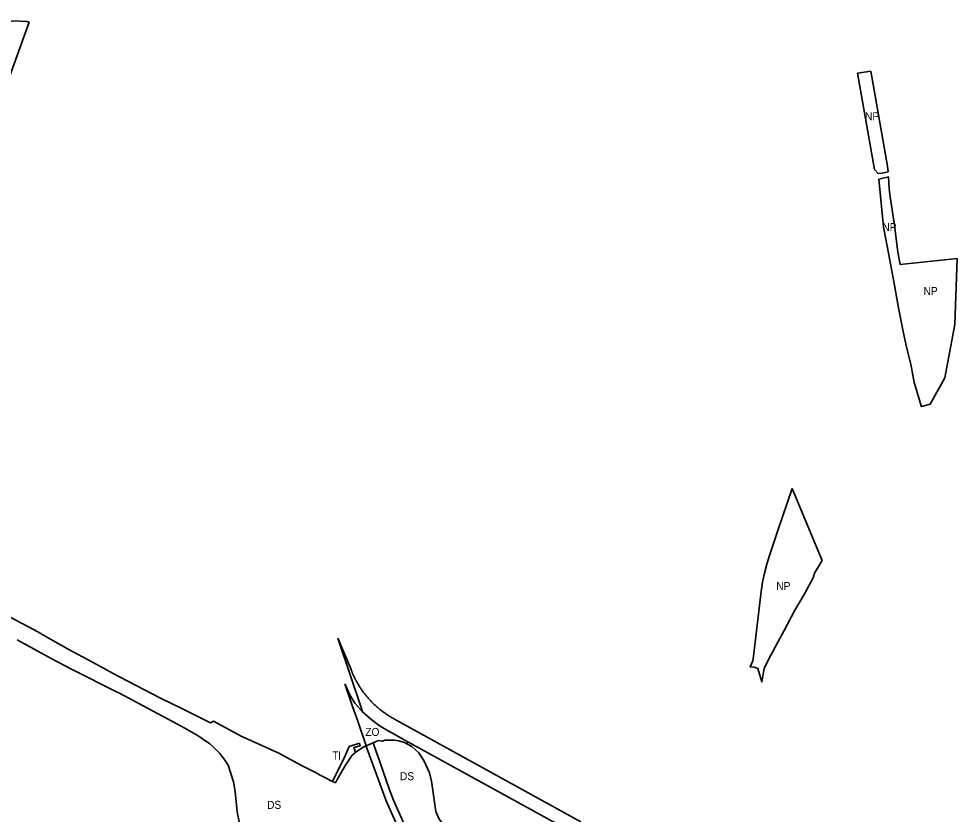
# Model space of a CAD drawing. Extents: x -650971 to -642489, y -1074311 to -1062745.
# Drawn here: x -647077 to -645670, y -1068619 to -1067426 of the extents above; entities that cross this region are included whole.
import ezdxf

# ---------------------------------------------------------------- set-up
doc = ezdxf.new("R2010")
doc.units = 0
doc.header["$LTSCALE"] = 4.8
for name, color, linetype, lineweight in [('24', 7, 'Continuous', 35), ('25', 7, 'Continuous', 35), ('30', 7, 'Continuous', 35), ('42', 7, 'Continuous', 35), ('48', 7, 'Continuous', 35), ('62', 7, 'Continuous', 35)]:
    doc.layers.add(name, color=color, linetype=linetype, lineweight=lineweight)

msp = doc.modelspace()

# ---------------------------------------------------------------- linework, layer by layer
at = {"layer": '24'}
for points in [[(-647099.2, -1068318.27), (-647053.75, -1068342.11), (-647044.93, -1068347.08), (-647040.77, -1068349.4), (-647002.71, -1068371.09), (-646967.64, -1068390), (-646938.95, -1068405.8), (-646936.47, -1068407.23), (-646864.48, -1068444.64), (-646832.29, -1068460.04), (-646789.49, -1068481.31), (-646787.55, -1068480.36), (-646785.05, -1068479.12), (-646743.69, -1068501.76), (-646686.84, -1068526.89), (-646653.21, -1068545.58), (-646631.18, -1068556.77), (-646625.86, -1068559.47), (-646620.94, -1068561.96), (-646606.59, -1068569.33)], [(-646746.32, -1068630.23), (-646749.35, -1068615.18), (-646752.59, -1068584.55), (-646753.35, -1068578.6), (-646754.92, -1068569.81), (-646763.1, -1068545.18), (-646768.95, -1068535.8), (-646775.44, -1068527.74), (-646779.93, -1068522.9), (-646785.34, -1068517.77), (-646790.66, -1068513.24), (-646799.79, -1068506.39), (-646807.82, -1068501.17), (-646828.2, -1068489.61), (-646854.18, -1068475.8), (-646927.06, -1068436.66), (-646929.56, -1068435.42), (-646997.06, -1068401.37), (-647029.23, -1068384.46), (-647032.91, -1068382.51), (-647079.16, -1068357.01)], [(-646598.635, -1068354.436), (-646578.881, -1068401.54), (-646578.62, -1068402.227), (-646578.355, -1068402.913), (-646578.087, -1068403.598), (-646577.815, -1068404.281), (-646577.539, -1068404.964), (-646577.26, -1068405.645), (-646576.977, -1068406.324), (-646576.691, -1068407.003), (-646576.4, -1068407.68), (-646576.107, -1068408.355), (-646575.809, -1068409.03), (-646575.508, -1068409.702), (-646575.204, -1068410.374), (-646574.896, -1068411.043), (-646574.584, -1068411.712), (-646574.269, -1068412.379), (-646573.95, -1068413.044), (-646573.628, -1068413.707), (-646573.302, -1068414.369), (-646572.973, -1068415.029), (-646572.64, -1068415.688), (-646572.304, -1068416.345)], [(-646561.544, -1068464.842), (-646564.78, -1068455.41), (-646579.62, -1068411.29), (-646598.635, -1068354.436)], [(-646572.304, -1068416.345), (-646571.964, -1068417), (-646571.621, -1068417.653), (-646571.275, -1068418.305), (-646570.925, -1068418.954), (-646570.571, -1068419.602), (-646570.215, -1068420.248), (-646569.854, -1068420.892), (-646569.491, -1068421.534), (-646569.124, -1068422.174), (-646568.754, -1068422.812), (-646568.381, -1068423.448), (-646568.004, -1068424.082), (-646567.624, -1068424.714), (-646567.241, -1068425.344), (-646566.854, -1068425.972), (-646566.465, -1068426.597), (-646566.072, -1068427.221), (-646565.676, -1068427.842), (-646565.277, -1068428.461), (-646564.874, -1068429.078), (-646564.469, -1068429.693), (-646564.06, -1068430.305), (-646563.648, -1068430.915), (-646563.234, -1068431.522), (-646562.816, -1068432.128), (-646562.395, -1068432.731), (-646561.971, -1068433.332), (-646561.204, -1068434.402), (-646560.426, -1068435.467), (-646559.637, -1068436.524), (-646558.837, -1068437.575), (-646558.027, -1068438.62), (-646557.206, -1068439.658), (-646556.375, -1068440.69), (-646555.534, -1068441.715), (-646554.682, -1068442.732), (-646553.82, -1068443.741), (-646552.948, -1068444.744), (-646552.067, -1068445.738), (-646551.175, -1068446.723), (-646550.273, -1068447.702), (-646549.362, -1068448.673), (-646548.442, -1068449.635), (-646547.511, -1068450.589), (-646546.572, -1068451.534), (-646545.623, -1068452.47), (-646544.666, -1068453.399), (-646543.699, -1068454.318), (-646542.724, -1068455.227), (-646541.739, -1068456.127), (-646540.747, -1068457.018), (-646539.745, -1068457.901), (-646538.736, -1068458.773), (-646537.718, -1068459.635), (-646536.693, -1068460.488), (-646535.659, -1068461.331), (-646534.618, -1068462.164), (-646533.569, -1068462.987), (-646532.513, -1068463.799), (-646531.449, -1068464.601), (-646530.378, -1068465.393), (-646529.3, -1068466.174), (-646528.216, -1068466.945), (-646527.125, -1068467.705), (-646526.027, -1068468.454), (-646524.923, -1068469.192), (-646523.812, -1068469.92), (-646522.696, -1068470.636), (-646521.574, -1068471.342), (-646520.446, -1068472.036), (-646519.312, -1068472.719), (-646518.173, -1068473.39), (-646517.029, -1068474.051), (-646515.88, -1068474.7), (-646514.726, -1068475.337), (-646513.45, -1068476.025), (-646234.342, -1068629.892)], [(-646493.511, -1068509.855), (-646523.105, -1068493.54), (-646535.245, -1068486.342), (-646544.525, -1068479.79), (-646553.677, -1068472.283), (-646561.544, -1068464.842)], [(-646572.02, -1068526.07), (-646569.61, -1068524.1), (-646559.72, -1068517.29), (-646556.22, -1068515.84)], [(-646556.22, -1068515.84), (-646555, -1068519.38), (-646526.1, -1068598.55), (-646486.23, -1068688.54)], [(-646545.57, -1068511.42), (-646537.71, -1068508.16), (-646531.9, -1068509.25), (-646528.18, -1068507.58), (-646514.39, -1068507.56), (-646507.4, -1068508.45), (-646498.48, -1068511.26), (-646495.416, -1068512.888)], [(-646470.65, -1068697.38), (-646515.09, -1068597.29), (-646516.07, -1068595.08), (-646519.14, -1068587.06), (-646521.81, -1068580.69), (-646535.84, -1068539.8), (-646541.06, -1068524.58), (-646545.57, -1068511.42)], [(-646495.416, -1068512.888), (-646487.92, -1068516.87), (-646477.41, -1068526.45), (-646469.51, -1068538.15), (-646461.14, -1068556.34), (-646458.03, -1068569.26), (-646451.82, -1068614.31), (-646446.54, -1068626.14), (-646425.11, -1068652.37), (-646422.32, -1068655.58), (-646413.45, -1068664.71), (-646404.83, -1068671.52), (-646340.36, -1068710.915), (-646337.93, -1068712.4), (-646331.26, -1068716.25), (-646288.59, -1068740.88), (-646229.44, -1068773.53), (-646161.45, -1068807.54), (-646159.1, -1068807.43), (-646150.26, -1068812.81)], [(-646145.083, -1068810.83), (-646204.654, -1068690.937), (-646209.179, -1068681.795), (-646213.659, -1068674.696), (-646221.348, -1068665.144), (-646228.691, -1068658.051), (-646236.707, -1068651.891), (-646243.997, -1068647.407), (-646493.511, -1068509.855)], [(-646606.59, -1068569.33), (-646602.21, -1068571.5), (-646599.75, -1068566.49), (-646587.28, -1068545.28), (-646577.07, -1068530.2), (-646572.02, -1068526.07)]]:
    msp.add_lwpolyline(points, dxfattribs=at)
at = {"layer": '25'}
for points in [[(-647346.944, -1067425.768), (-647315.89, -1067429.71), (-647296.75, -1067437.91), (-647294.31, -1067453.26), (-647292.51, -1067464.56), (-647290.23, -1067478.89), (-647267.49, -1067476.23), (-647252.99, -1067472.35), (-647243.39, -1067469.81), (-647103.55, -1067432.54), (-647084.77, -1067428.64), (-647064.87, -1067429.73), (-647061.252, -1067430.908)], [(-647061.252, -1067430.908), (-647108.971, -1067561.55), (-647155.592, -1067670.17), (-647198.088, -1067756.5), (-647210.537, -1067778.594)]]:
    msp.add_lwpolyline(points, dxfattribs=at)
at = {"layer": '30'}
for points in [[(-646606.59, -1068569.33), (-646602.01, -1068560.15), (-646590.31, -1068536.69), (-646581.64, -1068517.24), (-646566.33, -1068512.04)], [(-646566.33, -1068512.04), (-646565.04, -1068515.86), (-646574.48, -1068518.75), (-646572.02, -1068526.07)], [(-646572.02, -1068526.07), (-646577.07, -1068530.2), (-646587.28, -1068545.28), (-646599.75, -1068566.49), (-646602.21, -1068571.5), (-646606.59, -1068569.33)]]:
    msp.add_lwpolyline(points, dxfattribs=at)
at = {"layer": '42'}
for points in [[(-646588.07, -1068422.96), (-646580.625, -1068439.803), (-646572.984, -1068451.81), (-646561.544, -1068464.842)], [(-646556.22, -1068515.84), (-646568.87, -1068479.14), (-646576.4, -1068457.27), (-646588.07, -1068422.96)], [(-646561.544, -1068464.842), (-646553.677, -1068472.283), (-646544.525, -1068479.79), (-646535.245, -1068486.342), (-646523.105, -1068493.54), (-646493.511, -1068509.855), (-646495.416, -1068512.888)], [(-646495.416, -1068512.888), (-646498.48, -1068511.26), (-646507.4, -1068508.45), (-646514.39, -1068507.56), (-646528.18, -1068507.58), (-646531.9, -1068509.25), (-646537.71, -1068508.16), (-646545.57, -1068511.42), (-646556.22, -1068515.84)]]:
    msp.add_lwpolyline(points, dxfattribs=at)
at = {"layer": '48'}
for p, q in [((-645819.48, -1067507.57), (-645799.72, -1067504.47)), ((-645787.55, -1067666.46), (-645773.23, -1067662.67))]:
    msp.add_line(p, q, dxfattribs=at)
for points in [[(-645799.72, -1067504.47), (-645774.48, -1067646.99), (-645773.771, -1067655.463)], [(-645788.395, -1067658.038), (-645793.94, -1067651.61), (-645819.48, -1067507.57)], [(-645773.771, -1067655.463), (-645782.72, -1067657.28), (-645788.395, -1067658.038)], [(-645723.73, -1068007.49), (-645734.61, -1067971.28), (-645739.85, -1067943.75), (-645745.86, -1067920.32), (-645751.08, -1067894.5), (-645758.47, -1067856.55), (-645764.11, -1067825.26), (-645773.04, -1067777.35), (-645779.64, -1067743.41), (-645780.39, -1067737.84), (-645787.55, -1067666.46)], [(-645773.23, -1067662.67), (-645771.86, -1067680.92), (-645770.39, -1067692.63), (-645763.92, -1067735.14), (-645759.32, -1067775.89), (-645755.758, -1067794.254), (-645670.064, -1067785.335), (-645673.827, -1067884.119), (-645688.88, -1067964.087), (-645710.519, -1068003.601), (-645723.785, -1068007.069), (-645723.73, -1068007.49)], [(-645872.64, -1068238.08), (-645883.87, -1068256.88), (-645886.28, -1068264.22), (-645899.73, -1068289.25), (-645914.12, -1068313.54), (-645929.29, -1068342.91), (-645952.92, -1068386.53), (-645959.41, -1068400.16), (-645962.86, -1068420.15), (-645968.86, -1068400.15), (-645974.67, -1068398.28), (-645980.61, -1068397.35), (-645976.72, -1068388.53), (-645975.46, -1068381.74), (-645963.94, -1068284.44), (-645961.93, -1068270.74), (-645959.15, -1068257.17), (-645955.63, -1068243.79), (-645951.35, -1068230.61), (-645938.87, -1068193.06), (-645917.44, -1068129.99)], [(-645917.44, -1068129.99), (-645874.15, -1068234.44), (-645872.64, -1068238.08)]]:
    msp.add_lwpolyline(points, dxfattribs=at)

# ---------------------------------------------------------------- texts
at = {"layer": '62'}
for s, width, p in [('NP', 0.95, (-645808.298, -1067578)), ('NP', 0.95, (-645782.298, -1067744)), ('NP', 0.95, (-645720.583, -1067840.041)), ('NP', 0.95, (-645941.298, -1068282.326)), ('ZO', 0.95, (-646557.423, -1068501.188)), ('TI', 0.85, (-646606.476, -1068536.535)), ('DS', 0.95, (-646505.476, -1068567.535)), ('DS', 0.95, (-646704.709, -1068610.535))]:
    msp.add_text(s, height=12, dxfattribs=dict(at, width=width)).set_placement(p)

doc.saveas('drawing.dxf')
